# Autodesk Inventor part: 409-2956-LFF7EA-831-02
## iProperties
Created: 2010-09
Part Number: 409-2956-LFF7EA-831-02
Material: 3/8"OD TUBE - SS
Document SubType Name: Modeling
Designer: S. Boerckel
Engineer: Steve Boerckel
Mass: 166.544 g
Surface Area: 342.312 cm^2
Volume: 20.6119 cm^3
Density: 8.08 g/cm^3
Description: LOW PRESSURE GAUGE TUBE
LGTH: 21.055 in
Author: S. Boerckel
Revision Number: 0
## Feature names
1. Sweep1
